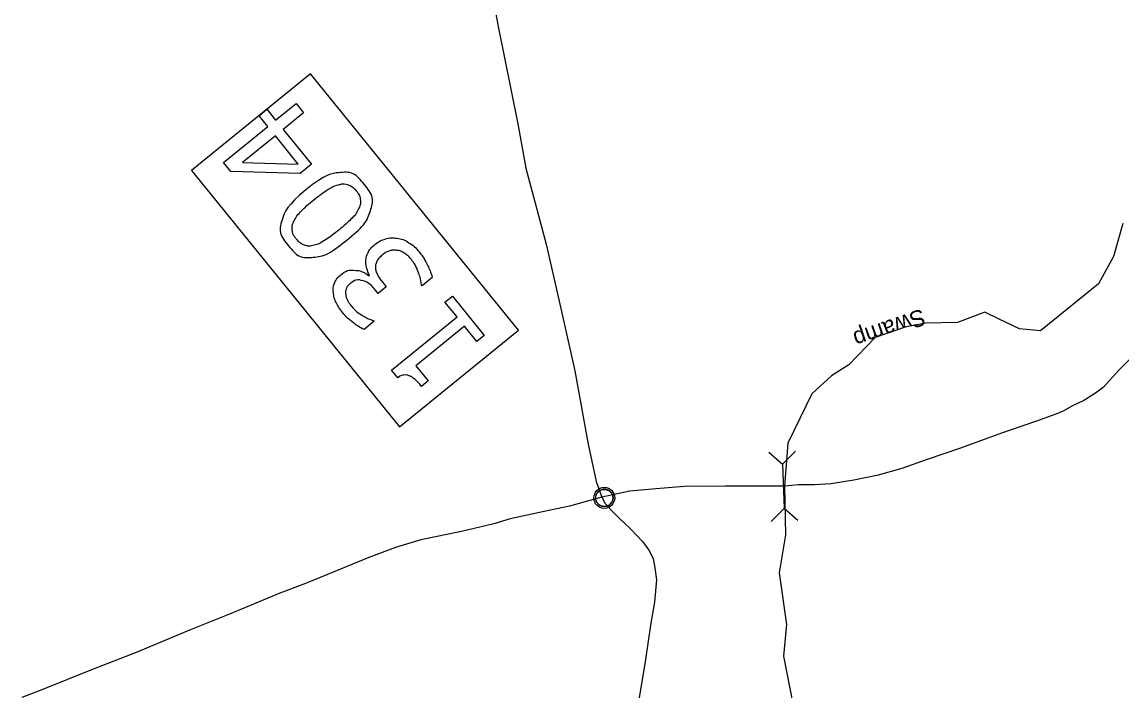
# Model space of a CAD drawing. Extents: x 2596159 to 2598075, y 851667 to 853493.
# Drawn here: x 2597073.5 to 2597143.5, y 851877.7 to 851920.2 of the extents above; entities that cross this region are included whole.
import ezdxf

# ---------------------------------------------------------------- set-up
doc = ezdxf.new("R2010")
doc.units = 0
doc.layers.add('Old_Level_1', color=7, linetype='Continuous')

msp = doc.modelspace()

# ---------------------------------------------------------------- linework, layer by layer
at = {"layer": 'Old_Level_1'}
for p, q in [((2597103.088, 851923.8), (2597103.8, 851919.893)), ((2597103.8, 851919.893), (2597105.042, 851913.706)), ((2597105.095, 851900.605), (2597091.868, 851916.879)), ((2597105.042, 851913.706), (2597105.551, 851910.878)), ((2597105.551, 851910.878), (2597106.846, 851906.063)), ((2597143.512, 851907.365), (2597142.904, 851905.269)), ((2597106.846, 851906.063), (2597107.779, 851901.983)), ((2597142.904, 851905.269), (2597141.958, 851903.547)), ((2597141.958, 851903.547), (2597138.268, 851900.564)), ((2597107.779, 851901.983), (2597108.663, 851898.008)), ((2597134.736, 851901.737), (2597132.991, 851901.079)), ((2597135.645, 851901.298), (2597134.736, 851901.737)), ((2597129.732, 851900.801), (2597127.766, 851900.129)), ((2597130.977, 851901.044), (2597129.732, 851900.801)), ((2597132.991, 851901.079), (2597130.977, 851901.044)), ((2597136.938, 851900.673), (2597135.645, 851901.298)), ((2597127.766, 851900.129), (2597126.085, 851898.399)), ((2597138.268, 851900.564), (2597136.938, 851900.673)), ((2597144.822, 851899.639), (2597143.285, 851898.106)), ((2597108.663, 851898.008), (2597109.495, 851893.459)), ((2597126.085, 851898.399), (2597124.98, 851897.694)), ((2597143.285, 851898.106), (2597142.267, 851896.954)), ((2597124.98, 851897.694), (2597123.731, 851896.559)), ((2597141.759, 851896.601), (2597141.031, 851896.124)), ((2597142.267, 851896.954), (2597141.759, 851896.601)), ((2597123.731, 851896.559), (2597122.215, 851893.42)), ((2597141.031, 851896.124), (2597140.269, 851895.766)), ((2597139.24, 851895.263), (2597137.951, 851894.796)), ((2597139.722, 851895.454), (2597139.24, 851895.263)), ((2597140.269, 851895.766), (2597139.722, 851895.454)), ((2597137.951, 851894.796), (2597135.803, 851894.051)), ((2597135.803, 851894.051), (2597133.198, 851893.106)), ((2597109.495, 851893.459), (2597110.033, 851890.99)), ((2597122.215, 851893.42), (2597121.995, 851890.7)), ((2597133.198, 851893.106), (2597131.068, 851892.375)), ((2597120.995, 851892.855), (2597121.874, 851892.077)), ((2597122.698, 851892.912), (2597121.874, 851892.077)), ((2597121.874, 851892.077), (2597121.969, 851889.282)), ((2597129.45, 851891.822), (2597127.944, 851891.389)), ((2597131.068, 851892.375), (2597129.45, 851891.822)), ((2597110.033, 851890.99), (2597110.385, 851889.992)), ((2597126.417, 851891.063), (2597124.958, 851890.83)), ((2597127.944, 851891.389), (2597126.417, 851891.063)), ((2597112.162, 851890.373), (2597110.385, 851889.992)), ((2597113.81, 851890.526), (2597112.162, 851890.373)), ((2597115.634, 851890.674), (2597113.81, 851890.526)), ((2597118.248, 851890.693), (2597115.634, 851890.674)), ((2597121.995, 851890.7), (2597118.248, 851890.693)), ((2597122.898, 851890.775), (2597121.995, 851890.7)), ((2597121.995, 851890.7), (2597122.071, 851887.609)), ((2597123.906, 851890.765), (2597122.898, 851890.775)), ((2597124.958, 851890.83), (2597123.906, 851890.765)), ((2597110.385, 851889.992), (2597108.333, 851889.416)), ((2597110.385, 851889.992), (2597110.603, 851889.6)), ((2597110.603, 851889.6), (2597111.027, 851889.128)), ((2597106.728, 851889.072), (2597104.566, 851888.609)), ((2597108.333, 851889.416), (2597106.728, 851889.072)), ((2597111.027, 851889.128), (2597111.516, 851888.641)), ((2597121.144, 851888.447), (2597121.969, 851889.282)), ((2597122.848, 851888.505), (2597121.969, 851889.282)), ((2597103.53, 851888.297), (2597101.459, 851887.818)), ((2597104.566, 851888.609), (2597103.53, 851888.297)), ((2597111.516, 851888.641), (2597112.198, 851887.992)), ((2597101.459, 851887.818), (2597098.887, 851887.277)), ((2597112.198, 851887.992), (2597112.992, 851887.16)), ((2597122.071, 851887.609), (2597121.659, 851885.177)), ((2597097.27, 851886.802), (2597095.57, 851886.168)), ((2597098.887, 851887.277), (2597097.27, 851886.802)), ((2597112.992, 851887.16), (2597113.368, 851886.621)), ((2597095.57, 851886.168), (2597093.408, 851885.271)), ((2597113.368, 851886.621), (2597113.501, 851886.389)), ((2597113.501, 851886.389), (2597113.645, 851886.067)), ((2597113.645, 851886.067), (2597113.755, 851885.513)), ((2597113.755, 851885.513), (2597113.868, 851884.735)), ((2597093.408, 851885.271), (2597091.542, 851884.519)), ((2597113.868, 851884.735), (2597113.728, 851883.317)), ((2597121.659, 851885.177), (2597122.117, 851881.91)), ((2597091.542, 851884.519), (2597089.917, 851883.886)), ((2597089.917, 851883.886), (2597086.727, 851882.563)), ((2597113.728, 851883.317), (2597113.484, 851881.866)), ((2597086.727, 851882.563), (2597084.291, 851881.592)), ((2597122.117, 851881.91), (2597121.939, 851879.886)), ((2597084.291, 851881.592), (2597080.784, 851880.133)), ((2597113.484, 851881.866), (2597113.161, 851879.683)), ((2597080.784, 851880.133), (2597077.954, 851879.025)), ((2597121.939, 851879.886), (2597122.358, 851877.74)), ((2597113.161, 851879.683), (2597112.506, 851875.786)), ((2597077.954, 851879.025), (2597074.892, 851877.79)), ((2597074.892, 851877.79), (2597073.528, 851877.271)), ((2597122.358, 851877.74), (2597122.735, 851875.782))]:
    msp.add_line(p, q, dxfattribs=at)
for points in [[(2597105.095, 851900.605), (2597091.868, 851916.879), (2597084.301, 851910.729), (2597097.528, 851894.454), (2597105.095, 851900.605)], [(2597089.092, 851914.623), (2597089.649, 851913.937), (2597090.949, 851914.993), (2597091.432, 851914.398), (2597090.133, 851913.342), (2597091.93, 851911.131), (2597091.217, 851910.552), (2597086.798, 851910.673), (2597086.334, 851911.243), (2597089.152, 851913.533), (2597088.595, 851914.219), (2597089.092, 851914.623)], [(2597089.636, 851912.938), (2597087.552, 851911.244), (2597091.091, 851911.148), (2597089.636, 851912.938)], [(2597095.582, 851904.049), (2597095.625, 851904.084)], [(2597096.458, 851903.62), (2597096.685, 851903.341), (2597096.173, 851902.924), (2597095.996, 851903.142)], [(2597099.607, 851903.945), (2597098.96, 851903.42), (2597098.923, 851903.466)], [(2597097.414, 851897.58), (2597097.024, 851898.06), (2597101.182, 851901.44), (2597100.417, 851902.382), (2597100.888, 851902.764)], [(2597100.888, 851902.764), (2597102.918, 851900.267), (2597102.447, 851899.884), (2597101.666, 851900.845), (2597098.574, 851898.332), (2597099.354, 851897.371), (2597098.932, 851897.028)], [(2597095.894, 851901.198), (2597095.919, 851901.167), (2597095.272, 851900.641)]]:
    msp.add_lwpolyline(points, dxfattribs=at)
msp.add_lwpolyline([(2597110.822, 851889.466), (2597110.787, 851889.446), (2597110.743, 851889.427), (2597110.69, 851889.411), (2597110.646, 851889.401), (2597110.6, 851889.394), (2597110.555, 851889.392), (2597110.514, 851889.394), (2597110.468, 851889.399), (2597110.418, 851889.408), (2597110.374, 851889.422), (2597110.337, 851889.436), (2597110.301, 851889.453), (2597110.264, 851889.472), (2597110.229, 851889.495), (2597110.204, 851889.513), (2597110.178, 851889.537), (2597110.156, 851889.556), (2597110.126, 851889.59), (2597110.107, 851889.614), (2597110.083, 851889.646), (2597110.065, 851889.677), (2597110.049, 851889.708), (2597110.034, 851889.741), (2597110.022, 851889.778), (2597110.008, 851889.828), (2597110, 851889.877), (2597109.997, 851889.921), (2597109.996, 851889.967), (2597109.998, 851889.999), (2597110.004, 851890.041), (2597110.012, 851890.083), (2597110.024, 851890.12), (2597110.037, 851890.16), (2597110.054, 851890.196), (2597110.073, 851890.229), (2597110.093, 851890.26), (2597110.113, 851890.288), (2597110.141, 851890.321), (2597110.164, 851890.345), (2597110.195, 851890.373), (2597110.228, 851890.398), (2597110.262, 851890.42), (2597110.296, 851890.439), (2597110.337, 851890.457), (2597110.377, 851890.473), (2597110.415, 851890.483), (2597110.462, 851890.492), (2597110.505, 851890.498), (2597110.546, 851890.5), (2597110.591, 851890.498), (2597110.642, 851890.491), (2597110.687, 851890.482), (2597110.728, 851890.47), (2597110.761, 851890.458), (2597110.809, 851890.435), (2597110.855, 851890.408), (2597110.89, 851890.382), (2597110.926, 851890.351), (2597110.948, 851890.329), (2597110.97, 851890.306), (2597110.995, 851890.275), (2597111.011, 851890.25), (2597111.032, 851890.216), (2597111.052, 851890.178), (2597111.065, 851890.147), (2597111.078, 851890.11), (2597111.087, 851890.076), (2597111.092, 851890.045), (2597111.1, 851889.99), (2597111.102, 851889.94), (2597111.099, 851889.893), (2597111.092, 851889.847), (2597111.085, 851889.812), (2597111.075, 851889.777), (2597111.055, 851889.724), (2597111.043, 851889.698), (2597111.028, 851889.671), (2597110.995, 851889.621), (2597110.963, 851889.581), (2597110.938, 851889.554), (2597110.905, 851889.524), (2597110.88, 851889.503), (2597110.842, 851889.477)], close=True, dxfattribs=at)
for centre, radius in [((2597110.545, 851889.945), 0.665), ((2597110.544, 851889.942), 0.541)]:
    msp.add_circle(centre, radius, dxfattribs=at)
for points in [[(2597091.572, 851909.506), (2597092.816, 851910.518), (2597093.714, 851910.602), (2597094.612, 851910.686), (2597095.276, 851909.869), (2597095.951, 851909.038), (2597095.672, 851908.177), (2597095.394, 851907.315), (2597094.171, 851906.321), (2597092.939, 851905.32), (2597092.036, 851905.229), (2597091.134, 851905.138), (2597090.466, 851905.959), (2597089.792, 851906.789), (2597090.078, 851907.657), (2597090.365, 851908.525), (2597091.572, 851909.506)], [(2597093.643, 851909.837), (2597093.303, 851909.741), (2597092.932, 851909.503), (2597092.561, 851909.266), (2597092.083, 851908.877), (2597091.611, 851908.494), (2597091.295, 851908.173), (2597090.979, 851907.852), (2597090.828, 851907.544), (2597090.677, 851907.241), (2597090.708, 851906.955), (2597090.74, 851906.67), (2597090.979, 851906.375), (2597091.215, 851906.084), (2597091.491, 851905.992), (2597091.767, 851905.9), (2597092.103, 851905.988), (2597092.418, 851906.069), (2597092.818, 851906.331), (2597093.219, 851906.592), (2597093.66, 851906.95), (2597094.144, 851907.344), (2597094.442, 851907.643), (2597094.74, 851907.941), (2597094.907, 851908.262), (2597095.066, 851908.561), (2597095.041, 851908.852), (2597095.016, 851909.143), (2597094.764, 851909.452), (2597094.528, 851909.743), (2597094.251, 851909.837), (2597093.974, 851909.931), (2597093.643, 851909.837)], [(2597095.384, 851904.995), (2597095.397, 851905.252), (2597095.52, 851905.512), (2597095.644, 851905.772), (2597095.963, 851906.032), (2597096.28, 851906.289), (2597096.637, 851906.388), (2597096.994, 851906.488), (2597097.358, 851906.439), (2597097.764, 851906.384), (2597098.123, 851906.153), (2597098.483, 851905.923), (2597098.788, 851905.548), (2597099.1, 851905.164), (2597099.311, 851904.718), (2597099.522, 851904.272), (2597099.607, 851903.945)], [(2597098.923, 851903.466), (2597098.882, 851903.871), (2597098.707, 851904.321), (2597098.531, 851904.771), (2597098.261, 851905.103), (2597098.103, 851905.299), (2597097.858, 851905.466), (2597097.614, 851905.633), (2597097.376, 851905.666), (2597097.123, 851905.698), (2597096.901, 851905.633), (2597096.68, 851905.569), (2597096.428, 851905.365), (2597096.18, 851905.163), (2597096.081, 851904.951), (2597095.982, 851904.739), (2597096.002, 851904.524), (2597096.02, 851904.306), (2597096.145, 851904.078), (2597096.271, 851903.85), (2597096.458, 851903.62)], [(2597095.625, 851904.084), (2597095.529, 851904.253), (2597095.452, 851904.509), (2597095.375, 851904.766), (2597095.384, 851904.995)], [(2597095.272, 851900.641), (2597094.985, 851900.773), (2597094.595, 851901.066), (2597094.204, 851901.36), (2597093.925, 851901.704), (2597093.65, 851902.042), (2597093.503, 851902.35), (2597093.355, 851902.658), (2597093.323, 851902.977), (2597093.29, 851903.321), (2597093.408, 851903.607), (2597093.525, 851903.893), (2597093.807, 851904.123), (2597094.192, 851904.435), (2597094.699, 851904.397), (2597095.207, 851904.358), (2597095.582, 851904.049)], [(2597095.996, 851903.142), (2597095.613, 851903.613), (2597095.188, 851903.734), (2597094.762, 851903.854), (2597094.383, 851903.546), (2597094.216, 851903.41), (2597094.148, 851903.236), (2597094.08, 851903.063), (2597094.103, 851902.87), (2597094.13, 851902.671), (2597094.223, 851902.494), (2597094.315, 851902.316), (2597094.472, 851902.124), (2597094.711, 851901.829), (2597095.087, 851901.583), (2597095.462, 851901.336), (2597095.894, 851901.198)], [(2597098.932, 851897.028), (2597098.774, 851897.223), (2597098.56, 851897.42), (2597098.346, 851897.617), (2597098.191, 851897.681), (2597097.998, 851897.761), (2597097.812, 851897.746), (2597097.626, 851897.731), (2597097.414, 851897.58)]]:
    msp.add_open_spline(points, degree=3, dxfattribs=at)

# ---------------------------------------------------------------- texts
msp.add_text('Swamp', height=1.0571, rotation=199.02937, dxfattribs=at).set_placement((2597130.729, 851901.984))

doc.saveas('drawing.dxf')
